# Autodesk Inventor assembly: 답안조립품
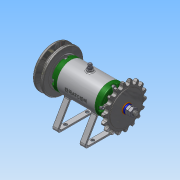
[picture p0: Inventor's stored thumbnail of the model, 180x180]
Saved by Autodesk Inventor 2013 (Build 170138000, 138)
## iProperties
Created: 2016-03
Part Number: 답안조립품
Document SubType Name: Assembly
Designer: Administrator
Author: Administrator
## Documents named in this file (16)
- C:\Users\Administrator\Desktop\460308V1016\답안조립품.iam
- C:\Users\Administrator\Desktop\460308V1016\본체.ipt
- C:\Users\Administrator\Desktop\460308V1016\V벨트풀리.ipt
- C:\Users\Administrator\Desktop\460308V1016\너트 M 8.ipt
- C:\Users\Administrator\Desktop\460308V1016\니플 M 6 x 0.75.ipt
- C:\Users\Administrator\Desktop\460308V1016\베어링 15 x 32 x 9.ipt
- C:\Users\Administrator\Desktop\460308V1016\볼트 M 6 x 8.ipt
- C:\Users\Administrator\Desktop\460308V1016\볼트 M4 x 12.ipt
- C:\Users\Administrator\Desktop\460308V1016\스프로킷.ipt
- C:\Users\Administrator\Desktop\460308V1016\스프링와셔 8.ipt
- C:\Users\Administrator\Desktop\460308V1016\오일 실 15 25 7.ipt
- C:\Users\Administrator\Desktop\460308V1016\와셔 6x11.5.ipt
- C:\Users\Administrator\Desktop\460308V1016\와셔 8x17.ipt
- C:\Users\Administrator\Desktop\460308V1016\축.ipt
- C:\Users\Administrator\Desktop\460308V1016\커버.ipt
- C:\Users\Administrator\Desktop\460308V1016\키 3 x 3 x 12.ipt
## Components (11 placed, 3 different names)
1. V벨트풀리:1
2. KS B 2023 6002 - 15 x 32 x 9:1
3. KS B 2023 6002 - 15 x 32 x 9:2
4. ISO 4762 M4 x 12:1
5. ISO 4762 M4 x 12:3
6. ISO 4762 M4 x 12:4
7. ISO 4762 M4 x 12:5
8. ISO 4762 M4 x 12:2
9. ISO 4762 M4 x 12:6
10. ISO 4762 M4 x 12:7
11. ISO 4762 M4 x 12:8
